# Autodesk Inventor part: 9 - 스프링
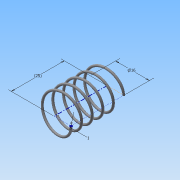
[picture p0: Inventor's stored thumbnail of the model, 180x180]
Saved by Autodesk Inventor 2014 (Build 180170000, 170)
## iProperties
Created: 2015-06
Part Number: 9 - 스프링
Material: 강철, 연강
Document SubType Name: Modeling
Designer: Administrator
Density: 1 g/cm^3
Appearance: 강철
Mass: 0.195266 g
Surface Area: 7.89194 cm^2
Volume: 0.195266 cm^3
Author: Administrator
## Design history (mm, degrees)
sketch "스케치1"
  geometry: L1 (0, 0)-(8, 0); L2 (8, 0)-(8, 21.5); L3 (8, 21.5)-(0, 21.5); L4 (0, 21.5)-(0, 0); C1 r 0.5 at (8, 0)
  constraints: 8 end point, 2 parallel, 1 centre point, 1 coincident, 1 horizontal, 1 perpendicular
  dimensions: "d0" = 21.5 distance between parallel lines of L1 L3 (derived); "d1" = 16 diameter of L2 L4; "d2" = 1 diameter of C1
feature "코일1" sketch "스케치1" pitch "d3" = 10; turns "d5" = 5; dims "d4" = 21.5 (= d0), "d6" = 0, angle "d7" = 90 deg, angle "d8" = 90 deg, "d9" = 0, "d10" = 0
node "작업 평면1"
sketch "스케치2"
  geometry: L1 (-8.5, 0)-(-7.5, 0) reference; 1 further point
  constraints: 1 horizontal alignment
extrude "돌출1" cut sketch "스케치2" distance "d12" = 10; taper "d13" = 0 deg
node "작업 평면2"
sketch "스케치3"
  geometry: L1 (-7.5, 0)-(-8.5, 0) reference; 1 further point
  constraints: 1 horizontal alignment
extrude "돌출2" cut sketch "스케치3" stored distance "d15" = 10; taper "d16" = 0 deg
node "솔리드1"
node "절단 모서리 투영1"
node "절단 모서리 투영2"
other parameters: "d11" = 0, "d14" = 21.5 (= d0)
